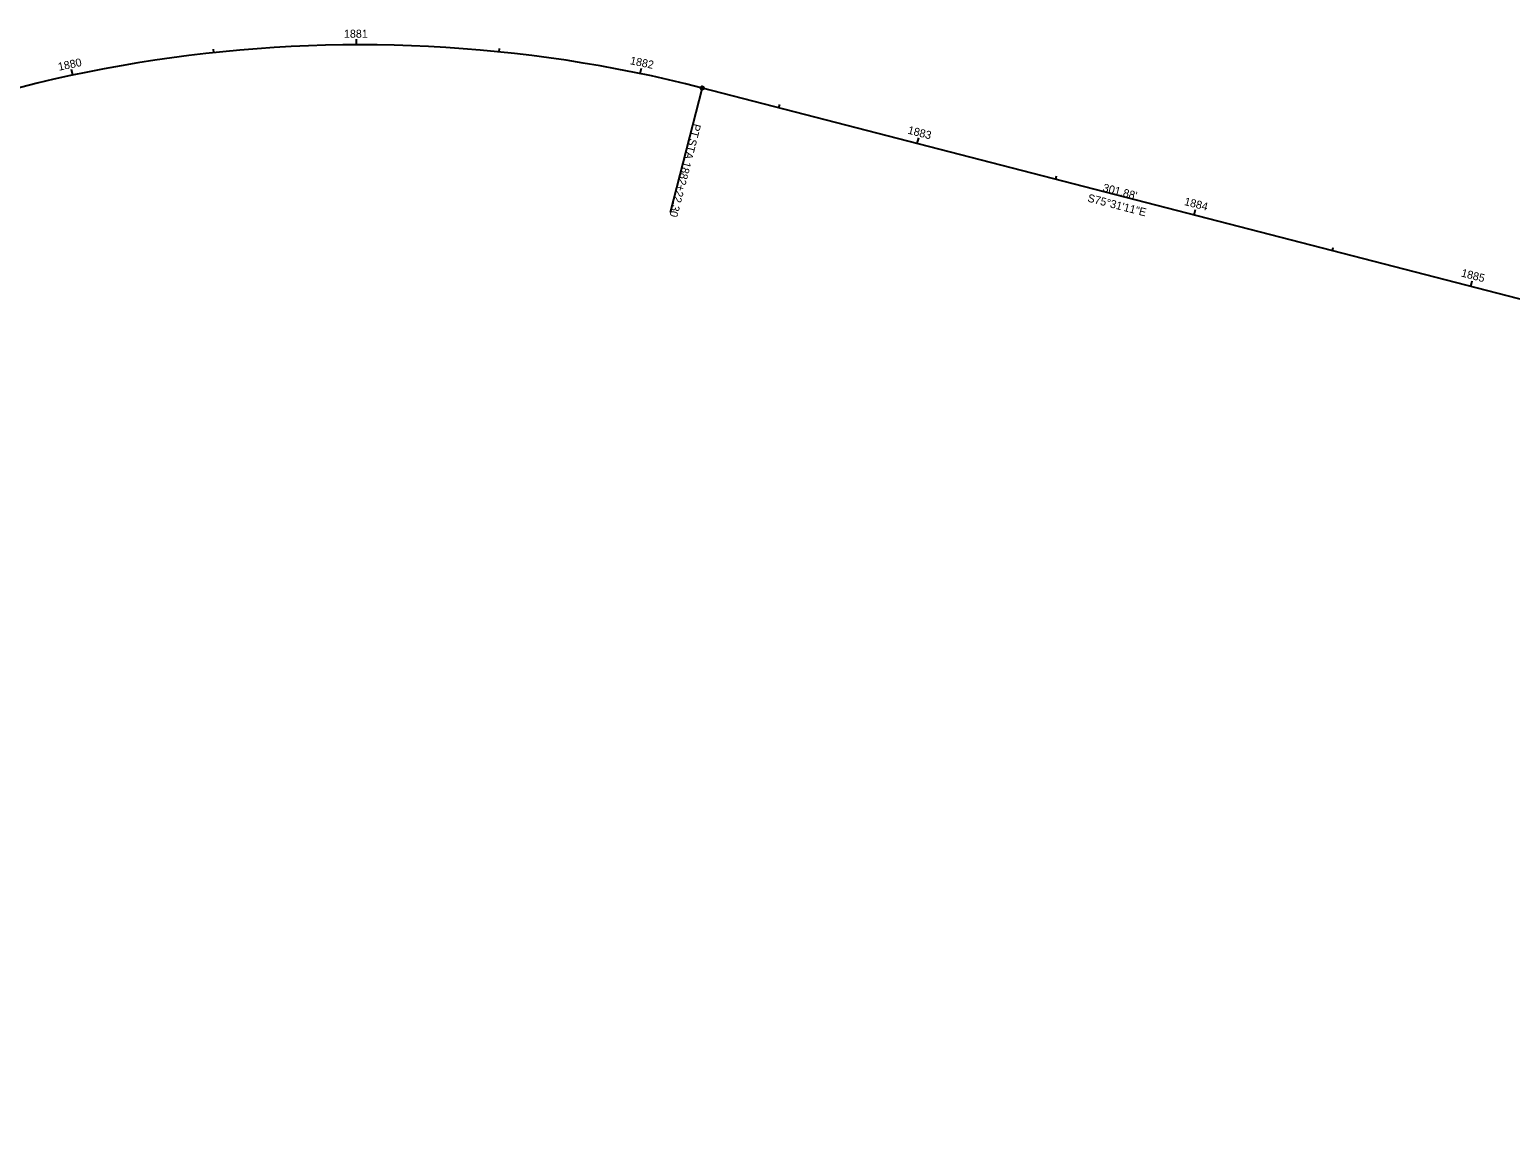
# Model space of a CAD drawing. Extents: x 199310 to 201359, y 391748 to 392909.
# Drawn here: x 199805 to 200323, y 392163 to 392546 of the extents above; entities that cross this region are included whole.
import ezdxf

# ---------------------------------------------------------------- set-up
doc = ezdxf.new("R2010")
doc.units = 0
for name, color, linetype in [('GE_X_Alignment_1000_Curve_Data', 7, 'Continuous'), ('GE_X_Alignment_1000_Stations', 7, 'Continuous'), ('GE_X_Alignment_100_Curve_Data', 7, 'Continuous'), ('GE_X_Alignment_100_Stations', 7, 'Continuous'), ('GE_X_Alignment_500_Stations', 7, 'Continuous')]:
    doc.layers.add(name, color=color, linetype=linetype)

msp = doc.modelspace()

# ---------------------------------------------------------------- linework, layer by layer
at = {"layer": 'GE_X_Alignment_1000_Stations'}
for p, q in [((199919.54, 392540.31), (199919.53, 392542.31)), ((199869.63, 392537.59), (199869.51, 392538.78)), ((199969.45, 392537.86), (199969.58, 392539.05)), ((199820.28, 392529.71), (199819.86, 392531.67)), ((200018.85, 392530.25), (200019.26, 392532.21)), ((200067.39, 392518.29), (200067.69, 392519.45)), ((200115.8, 392505.79), (200116.3, 392507.72)), ((200164.21, 392493.29), (200164.52, 392494.45)), ((200212.63, 392480.78), (200213.13, 392482.72)), ((200261.04, 392468.28), (200261.34, 392469.44)), ((200309.45, 392455.78), (200309.95, 392457.71))]:
    msp.add_line(p, q, dxfattribs=at)
at = {"layer": 'GE_X_Alignment_100_Stations'}
msp.add_line((200040.57, 392525.22), (200332.86, 392449.73), dxfattribs=at)
msp.add_arc((199920.84, 392058.02), 482.29, 75.626, 167.3677, dxfattribs=at)
at = {"layer": 'GE_X_Alignment_500_Stations'}
msp.add_line((200040.57, 392525.22), (200029.32, 392481.65), dxfattribs=at)
msp.add_circle((200040.57, 392525.22), 0.6, dxfattribs=at)

# ---------------------------------------------------------------- texts
at = {"layer": 'GE_X_Alignment_1000_Curve_Data'}
msp.add_text("301.88'", height=2.8, rotation=345.5196, dxfattribs=at).set_placement((200180.49, 392489.12))
at = {"layer": 'GE_X_Alignment_1000_Stations'}
for s, rotation, p in [('1881', 0.1552, (199915.19, 392542.8)), ('1880', 12.0351, (199815.47, 392531.24)), ('1882', 348.2752, (200015.12, 392533.58)), ('1883', 345.5196, (200112.25, 392509.29)), ('1884', 345.5196, (200208.99, 392484.3)), ('1885', 345.5196, (200305.89, 392459.28))]:
    msp.add_text(s, height=2.8, rotation=rotation, dxfattribs=at).set_placement(p)
at = {"layer": 'GE_X_Alignment_100_Curve_Data'}
msp.add_text('S75°31\'11"E', height=2.8, rotation=345.5196, dxfattribs=at).set_placement((200175.15, 392485.5))
at = {"layer": 'GE_X_Alignment_500_Stations'}
for s, p in [('PT', (200037.44, 392512.94)), (' STA. ', (200036.35, 392508.73)), ('1882+22.30', (200034.02, 392499.7))]:
    msp.add_text(s, height=2.8, rotation=255.5196, dxfattribs=at).set_placement(p)

doc.saveas('drawing.dxf')
